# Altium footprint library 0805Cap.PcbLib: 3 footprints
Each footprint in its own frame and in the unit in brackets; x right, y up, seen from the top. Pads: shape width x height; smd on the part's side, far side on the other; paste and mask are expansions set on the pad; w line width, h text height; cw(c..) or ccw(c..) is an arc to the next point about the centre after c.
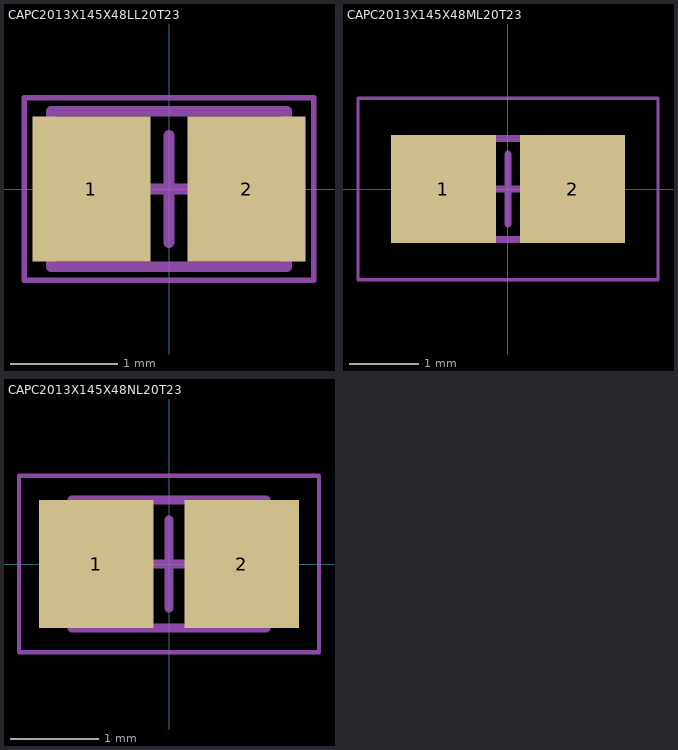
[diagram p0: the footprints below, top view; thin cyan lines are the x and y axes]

## CAPC2013X145X48LL20T23 [mm] "Chip Capacitor, 2-Leads, Body 2.00x1.25mm, IPC High Density"
height 1.45
pads (2):
  rect 1.1x1.35 smd: 1(-0.725,0) 2(0.725,0)
Mechanical 13:
  lines w0.1: -1.1,-0.725 -1.1,0.725 1.1,0.725 1.1,-0.725 -1.1,-0.725
Mechanical 15:
  lines w0.05: -1.35,-0.85 -1.35,0.85 1.35,0.85 1.35,-0.85 -1.35,-0.85
  lines w0.1: -0.5,0 0.5,0 ; 0,-0.5 0,0.5
3D body: height 1.45, standoff 0, extent -0.62,-0.725 0.62,0.725
3D body: height 1.45, standoff 0, extent -1.1,-0.725 -0.62,0.725
3D body: height 1.45, standoff 0, extent 0.62,-0.725 1.1,0.725

## CAPC2013X145X48ML20T23 [mm] "Chip Capacitor, 2-Leads, Body 2.00x1.25mm, IPC Low Density"
height 1.45
pads (2):
  rect 1.5x1.55 smd: 1(-0.925,0) 2(0.925,0)
Mechanical 13:
  lines w0.1: -1.1,-0.725 -1.1,0.725 1.1,0.725 1.1,-0.725 -1.1,-0.725
Mechanical 15:
  lines w0.05: -2.15,-1.3 -2.15,1.3 2.15,1.3 2.15,-1.3 -2.15,-1.3
  lines w0.1: -0.5,0 0.5,0 ; 0,-0.5 0,0.5
3D body: height 1.45, standoff 0, extent -0.62,-0.725 0.62,0.725
3D body: height 1.45, standoff 0, extent -1.1,-0.725 -0.62,0.725
3D body: height 1.45, standoff 0, extent 0.62,-0.725 1.1,0.725

## CAPC2013X145X48NL20T23 [mm] "Chip Capacitor, 2-Leads, Body 2.00x1.25mm, IPC Medium Density"
height 1.45
pads (2):
  rect 1.3x1.45 smd: 1(-0.825,0) 2(0.825,0)
Mechanical 13:
  lines w0.1: -1.1,-0.725 -1.1,0.725 1.1,0.725 1.1,-0.725 -1.1,-0.725
Mechanical 15:
  lines w0.05: -1.7,-1 -1.7,1 1.7,1 1.7,-1 -1.7,-1
  lines w0.1: -0.5,0 0.5,0 ; 0,-0.5 0,0.5
3D body: height 1.45, standoff 0, extent -0.62,-0.725 0.62,0.725
3D body: height 1.45, standoff 0, extent -1.1,-0.725 -0.62,0.725
3D body: height 1.45, standoff 0, extent 0.62,-0.725 1.1,0.725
